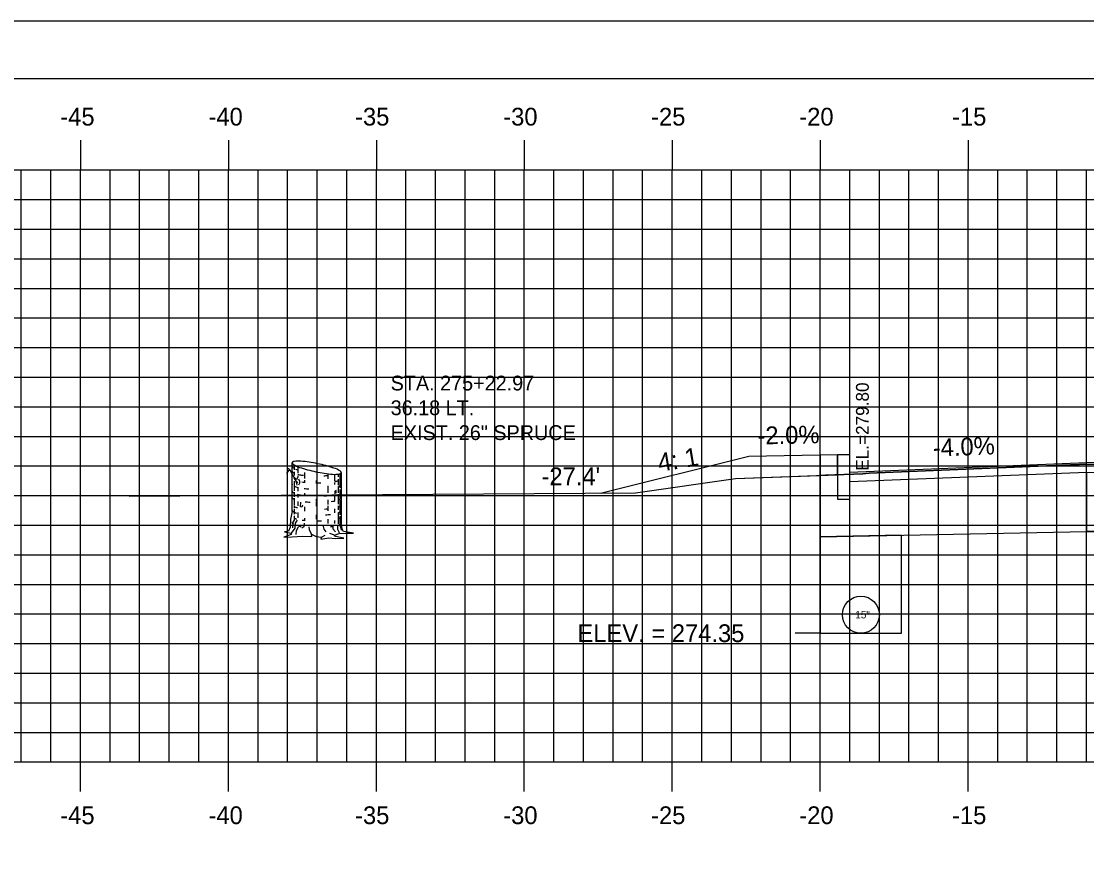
# Model space of a CAD drawing. Extents: x 853340 to 853510, y 366268 to 366378.
# Drawn here: x 853376.1 to 853412.11, y 366350.13 to 366378.18 of the extents above; entities that cross this region are included whole.
import ezdxf

# ---------------------------------------------------------------- set-up
doc = ezdxf.new("R2010")
doc.units = 0
for name, color, linetype in [('ANNOTATION', 7, 'Continuous'), ('BORDER', 7, 'Continuous'), ('D_Curb_Type_1_Lt', 7, 'Continuous'), ('D_Roadway_Edge_TW', 7, 'Continuous'), ('D_Roadway_FinishedGrade', 7, 'Continuous'), ('D_Roadway_SubGrade', 7, 'Continuous'), ('D_Text_Monospaced', 7, 'Continuous'), ('D_Text_Standard', 7, 'Continuous'), ('H_V ANNOTATION', 7, 'Continuous'), ('JUNK COM EXC', 7, 'Continuous'), ('JUNK FILL', 7, 'Continuous'), ('junk strct exc', 7, 'Continuous'), ('MAJOR', 7, 'Continuous'), ('MINOR', 7, 'Continuous'), ('PDRAIN', 7, 'Continuous'), ('PLOT BOUNDARY', 7, 'Continuous'), ('S_Roadway_Centerline', 7, 'Continuous'), ('S_Trees_Conifer_Pay', 7, 'Continuous')]:
    doc.layers.add(name, color=color, linetype=linetype)

msp = doc.modelspace()

# ---------------------------------------------------------------- linework, layer by layer
at = {"layer": 'BORDER'}
msp.add_line((853508.1, 366376.236), (853348.1, 366376.236), dxfattribs=at)
at = {"layer": 'D_Curb_Type_1_Lt'}
msp.add_lwpolyline([(853403.683, 366363.536), (853403.683, 366362.036), (853404.1, 366362.036), (853404.1, 366363.536)], close=True, dxfattribs=at)
at = {"layer": 'D_Roadway_Edge_TW'}
msp.add_lwpolyline([(853404.1, 366362.952), (853412.1, 366363.272), (853423.1, 366363.28), (853434.1, 366363.06), (853442.1, 366362.74)], dxfattribs=at)
at = {"layer": 'D_Roadway_FinishedGrade'}
msp.add_line((853400.683, 366363.476), (853395.722, 366362.235), dxfattribs=at)
msp.add_lwpolyline([(853403.683, 366363.536), (853400.683, 366363.476)], dxfattribs=at)
at = {"layer": 'D_Roadway_SubGrade'}
for points in [[(853403.1, 366363.524), (853403.1, 366360.759)], [(853403.1, 366360.759), (853412.107, 366360.939), (853412.107, 366362.939), (853404.1, 366362.619)]]:
    msp.add_lwpolyline(points, dxfattribs=at)
msp.add_lwpolyline([(853412.107, 366360.939), (853412.107, 366362.939), (853423.107, 366362.947), (853434.107, 366362.727), (853434.107, 366360.727), (853423.107, 366360.947)], close=True, dxfattribs=at)
at = {"layer": 'D_Text_Standard'}
msp.add_lwpolyline([(853403.1, 366357.506), (853402.939, 366357.506), (853402.259, 366357.506)], dxfattribs=at)
at = {"layer": 'JUNK COM EXC'}
msp.add_lwpolyline([(853403.1, 366362.838), (853403.1, 366360.759), (853412.107, 366360.939), (853423.107, 366360.947), (853443.101, 366360.548), (853443.1, 366362.612), (853435.895, 366362.863), (853428.824, 366363.051), (853423.1, 366363.253), (853411.854, 366363.201), (853411.562, 366363.195), (853404.759, 366362.908), (853404.544, 366362.894), (853403.28, 366362.845), (853403.1, 366362.838)], dxfattribs=at)
at = {"layer": 'JUNK FILL'}
msp.add_lwpolyline([(853403.683, 366362.861), (853403.683, 366363.536), (853400.683, 366363.476), (853395.722, 366362.235), (853396.858, 366362.243), (853400.236, 366362.728)], close=True, dxfattribs=at)
at = {"layer": 'junk strct exc'}
msp.add_lwpolyline([(853403.1, 366360.759), (853403.1, 366357.506), (853405.85, 366357.506), (853405.85, 366360.814)], close=True, dxfattribs=at)
at = {"layer": 'MAJOR'}
for p, q in [((853378.1, 366374.158), (853378.1, 366373.156)), ((853383.1, 366374.158), (853383.1, 366373.156)), ((853388.1, 366374.158), (853388.1, 366373.156)), ((853393.1, 366374.158), (853393.1, 366373.156)), ((853398.1, 366374.158), (853398.1, 366373.156)), ((853403.1, 366374.158), (853403.1, 366373.156)), ((853408.1, 366374.158), (853408.1, 366373.156)), ((853353.1, 366373.156), (853493.1, 366373.156)), ((853353.1, 366373.156), (853493.1, 366373.156)), ((853378.1, 366353.156), (853378.1, 366373.156)), ((853383.1, 366353.156), (853383.1, 366373.156)), ((853388.1, 366353.156), (853388.1, 366373.156)), ((853393.1, 366353.156), (853393.1, 366373.156)), ((853398.1, 366353.156), (853398.1, 366373.156)), ((853403.1, 366353.156), (853403.1, 366373.156)), ((853408.1, 366353.156), (853408.1, 366373.156)), ((853353.1, 366368.156), (853493.1, 366368.156)), ((853353.1, 366363.156), (853493.1, 366363.156)), ((853353.1, 366358.156), (853493.1, 366358.156)), ((853353.1, 366353.156), (853493.1, 366353.156)), ((853353.1, 366353.156), (853493.1, 366353.156)), ((853378.1, 366352.154), (853378.1, 366353.156)), ((853383.1, 366352.154), (853383.1, 366353.156)), ((853388.1, 366352.154), (853388.1, 366353.156)), ((853393.1, 366352.154), (853393.1, 366353.156)), ((853398.1, 366352.154), (853398.1, 366353.156)), ((853403.1, 366352.154), (853403.1, 366353.156)), ((853408.1, 366352.154), (853408.1, 366353.156))]:
    msp.add_line(p, q, dxfattribs=at)
at = {"layer": 'MINOR'}
for p, q in [((853376.1, 366353.156), (853376.1, 366373.156)), ((853377.1, 366353.156), (853377.1, 366373.156)), ((853379.1, 366353.156), (853379.1, 366373.156)), ((853380.1, 366353.156), (853380.1, 366373.156)), ((853381.1, 366353.156), (853381.1, 366373.156)), ((853382.1, 366353.156), (853382.1, 366373.156)), ((853384.1, 366353.156), (853384.1, 366373.156)), ((853385.1, 366353.156), (853385.1, 366373.156)), ((853386.1, 366353.156), (853386.1, 366373.156)), ((853387.1, 366353.156), (853387.1, 366373.156)), ((853389.1, 366353.156), (853389.1, 366373.156)), ((853390.1, 366353.156), (853390.1, 366373.156)), ((853391.1, 366353.156), (853391.1, 366373.156)), ((853392.1, 366353.156), (853392.1, 366373.156)), ((853394.1, 366353.156), (853394.1, 366373.156)), ((853395.1, 366353.156), (853395.1, 366373.156)), ((853396.1, 366353.156), (853396.1, 366373.156)), ((853397.1, 366353.156), (853397.1, 366373.156)), ((853399.1, 366353.156), (853399.1, 366373.156)), ((853400.1, 366353.156), (853400.1, 366373.156)), ((853401.1, 366353.156), (853401.1, 366373.156)), ((853402.1, 366353.156), (853402.1, 366373.156)), ((853404.1, 366353.156), (853404.1, 366373.156)), ((853405.1, 366353.156), (853405.1, 366373.156)), ((853406.1, 366353.156), (853406.1, 366373.156)), ((853407.1, 366353.156), (853407.1, 366373.156)), ((853409.1, 366353.156), (853409.1, 366373.156)), ((853410.1, 366353.156), (853410.1, 366373.156)), ((853411.1, 366353.156), (853411.1, 366373.156)), ((853412.1, 366353.156), (853412.1, 366373.156)), ((853353.1, 366372.156), (853493.1, 366372.156)), ((853353.1, 366371.156), (853493.1, 366371.156)), ((853353.1, 366370.156), (853493.1, 366370.156)), ((853353.1, 366369.156), (853493.1, 366369.156)), ((853353.1, 366367.156), (853493.1, 366367.156)), ((853353.1, 366366.156), (853493.1, 366366.156)), ((853353.1, 366365.156), (853493.1, 366365.156)), ((853353.1, 366364.156), (853493.1, 366364.156)), ((853353.1, 366362.156), (853493.1, 366362.156)), ((853353.1, 366361.156), (853493.1, 366361.156)), ((853353.1, 366360.156), (853493.1, 366360.156)), ((853353.1, 366359.156), (853493.1, 366359.156)), ((853353.1, 366357.156), (853493.1, 366357.156)), ((853353.1, 366356.156), (853493.1, 366356.156)), ((853353.1, 366355.156), (853493.1, 366355.156)), ((853353.1, 366354.156), (853493.1, 366354.156))]:
    msp.add_line(p, q, dxfattribs=at)
at = {"layer": 'PDRAIN'}
msp.add_lwpolyline([(853403.1, 366360.759), (853403.1, 366357.506), (853405.85, 366357.506), (853405.85, 366360.814)], dxfattribs=at)
msp.add_circle((853404.475, 366358.131), 0.625, dxfattribs=at)
at = {"layer": 'PLOT BOUNDARY'}
msp.add_lwpolyline([(853340.007, 366268.177), (853510.007, 366268.177), (853510.007, 366378.177), (853340.007, 366378.177)], close=True, dxfattribs=at)
at = {"layer": 'S_Roadway_Centerline'}
msp.add_lwpolyline([(853379.745, 366362.132), (853396.858, 366362.243), (853400.236, 366362.728), (853403.28, 366362.845), (853404.544, 366362.894), (853404.759, 366362.908), (853411.562, 366363.195), (853411.854, 366363.201), (853423.1, 366363.253), (853428.824, 366363.051), (853435.895, 366362.863), (853448.102, 366362.438), (853448.825, 366362.419), (853451.873, 366362.862), (853452.264, 366362.884), (853453.558, 366362.897), (853453.702, 366362.932), (853455.448, 366363.065), (853466.573, 366363.351)], dxfattribs=at)
at = {"layer": 'S_Trees_Conifer_Pay'}
for p, q in [((853385.252, 366361.618), (853385.252, 366363.265)), ((853385.323, 366363.193), (853385.323, 366363.03)), ((853385.441, 366363.132), (853385.441, 366362.909)), ((853385.323, 366362.963), (853385.323, 366362.835)), ((853385.441, 366362.82), (853385.441, 366362.773)), ((853385.669, 366362.936), (853385.669, 366362.736)), ((853386.465, 366362.894), (853386.465, 366362.726)), ((853386.685, 366362.873), (853386.685, 366362.641)), ((853386.81, 366362.881), (853386.81, 366362.784)), ((853386.869, 366362.892), (853386.869, 366362.421)), ((853386.916, 366361.208), (853386.916, 366362.93)), ((853385.323, 366362.648), (853385.323, 366362.312)), ((853385.384, 366362.637), (853385.435, 366362.577)), ((853385.441, 366362.438), (853385.441, 366362.306)), ((853385.669, 366362.679), (853385.669, 366362.59)), ((853386.06, 366362.662), (853386.06, 366362.567)), ((853386.465, 366362.489), (853386.465, 366362.252)), ((853386.685, 366362.6), (853386.685, 366362.526)), ((853386.81, 366362.709), (853386.81, 366362.505)), ((853386.81, 366362.448), (853386.81, 366362.248)), ((853385.323, 366362.275), (853385.323, 366362.112)), ((853385.323, 366362.065), (853385.323, 366361.848)), ((853385.441, 366362.195), (853385.441, 366362.085)), ((853385.669, 366362.242), (853385.669, 366362.137)), ((853386.06, 366362.049), (853386.06, 366361.974)), ((853386.685, 366362.123), (853386.685, 366361.984)), ((853386.81, 366362.201), (853386.81, 366361.865)), ((853386.869, 366362.357), (853386.869, 366362.049)), ((853385.323, 366361.818), (853385.323, 366361.744)), ((853385.323, 366361.703), (853385.323, 366361.53)), ((853385.441, 366361.95), (853385.441, 366361.808)), ((853385.669, 366361.77), (853385.669, 366361.624)), ((853386.06, 366361.95), (853386.06, 366361.801)), ((853386.465, 366362.007), (853386.465, 366361.855)), ((853386.465, 366361.812), (853386.465, 366361.639)), ((853386.685, 366361.713), (853386.685, 366361.571)), ((853386.81, 366361.812), (853386.81, 366361.676)), ((853386.869, 366362.001), (853386.869, 366361.509)), ((853385.441, 366361.581), (853385.441, 366361.408)), ((853385.669, 366361.392), (853385.669, 366361.303)), ((853386.06, 366361.509), (853386.06, 366361.356)), ((853386.465, 366361.361), (853386.465, 366361.208)), ((853386.81, 366361.577), (853386.81, 366361.198)), ((853386.869, 366361.455), (853386.869, 366361.208)), ((853386.685, 366361.309), (853386.685, 366361.215)), ((853386.248, 366360.751), (853386.374, 366360.815)), ((853386.685, 366360.815), (853386.522, 366360.879))]:
    msp.add_line(p, q, dxfattribs=at)
for points in [[(853385.206, 366362.996), (853385.131, 366363.004), (853385.058, 366362.905)], [(853385.435, 366362.763), (853385.398, 366362.689), (853385.351, 366362.746), (853385.293, 366362.814), (853385.201, 366363.008), (853385.136, 366363.055), (853385.106, 366363.062)], [(853385.421, 366362.51), (853385.384, 366362.637), (853385.32, 366362.753), (853385.289, 366362.82), (853385.22, 366362.967)], [(853385.468, 366362.726), (853385.499, 366362.641), (853385.503, 366362.574), (853385.472, 366362.51)], [(853386.737, 366362.236), (853386.743, 366362.331), (853386.699, 366362.308), (853386.699, 366362.213)], [(853385.598, 366361.837), (853385.585, 366361.76), (853385.538, 366361.77), (853385.551, 366361.937)], [(853385.252, 366361.618), (853385.201, 366361.356), (853385.184, 366361.083), (853385.127, 366360.957), (853384.991, 366360.927), (853385.221, 366360.889), (853385.221, 366360.889), (853385.215, 366360.842), (853384.968, 366360.747), (853385.242, 366360.764), (853385.598, 366360.784), (853385.919, 366360.774), (853385.913, 366360.856), (853386.061, 366360.774), (853386.248, 366360.751), (853386.224, 366360.683), (853386.491, 366360.726), (853386.712, 366360.7), (853387.005, 366360.717), (853386.716, 366360.774), (853386.685, 366360.815), (853386.848, 366360.873), (853387.085, 366360.883), (853387.325, 366360.883), (853386.984, 366360.941), (853386.942, 366361.021), (853386.916, 366361.208)], [(853385.425, 366361.33), (853385.351, 366361.225), (853385.346, 366361.052), (853385.221, 366360.889)], [(853385.326, 366361.476), (853385.32, 366361.33), (853385.273, 366361.262), (853385.262, 366361.062)], [(853385.384, 366360.836), (853385.398, 366360.974), (853385.472, 366361.103)], [(853385.662, 366361.225), (853385.652, 366361.099), (853385.577, 366361.056)], [(853385.913, 366360.856), (853385.839, 366360.998), (853385.829, 366361.099)], [(853386.401, 366360.927), (853386.333, 366361.021), (853386.306, 366361.161)], [(853386.627, 366361.167), (853386.627, 366361.035), (853386.716, 366360.936)], [(853386.79, 366361.14), (853386.784, 366361.025), (853386.837, 366360.936), (853386.848, 366360.873)], [(853386.868, 366361.161), (853386.889, 366361.083), (853386.909, 366360.988)]]:
    msp.add_lwpolyline(points, dxfattribs=at)
for centre, radius, start, end in [((853385.275, 366363.265), 0.0226, 156.5926, 168.2806), ((853385.275, 366363.265), 0.0226, 168.2806, 179.9685), ((853385.278, 366363.265), 0.0264, 179.9685, 190.7806), ((853385.283, 366363.266), 0.0314, 190.7806, 203.4842), ((853385.285, 366363.139), 0.0334, 185.7849, 196.0515), ((853385.295, 366363.142), 0.0441, 196.0515, 210), ((853385.278, 366363.264), 0.0264, 145.7806, 156.5926), ((853385.303, 366363.275), 0.0527, 203.4842, 213.2806), ((853385.282, 366363.261), 0.0314, 133.077, 145.7806), ((853385.311, 366363.151), 0.0624, 210, 228.7494), ((853385.327, 366363.291), 0.0817, 213.2806, 227.6113), ((853385.297, 366363.245), 0.0527, 123.2806, 133.077), ((853385.313, 366363.221), 0.0817, 108.9499, 123.2806), ((853385.441, 366363.415), 0.251, 227.6113, 235.7806), ((853385.367, 366363.062), 0.251, 100.7806, 108.9499), ((853385.751, 366363.871), 0.802, 235.7806, 251.9406), ((853385.47, 366362.52), 0.802, 84.6206, 100.7806), ((853385.06, 366358.162), 5.179, 78.2806, 84.6206), ((853385.06, 366358.162), 5.179, 71.9406, 78.2806), ((853385.285, 366362.984), 0.0334, 185.7849, 196.0515), ((853385.295, 366362.987), 0.0441, 196.0515, 210), ((853385.311, 366362.997), 0.0624, 210, 228.7494), ((853385.384, 366363.234), 0.172, 228.7494, 240), ((853385.384, 366363.079), 0.172, 228.7494, 240), ((853385.583, 366363.424), 0.571, 240, 242.9763), ((853385.583, 366363.579), 0.571, 247.5868, 255.5683), ((853385.583, 366363.424), 0.571, 255.6333, 261.8968), ((853387.108, 366368.033), 5.179, 251.9406, 258.2806), ((853386.084, 366366.942), 4.124, 261.8968, 263.762), ((853387.108, 366368.033), 5.179, 258.2806, 264.6206), ((853386.084, 366366.942), 4.124, 273.2669, 275.3045), ((853386.697, 366363.675), 0.802, 264.6206, 280.7806), ((853386.417, 366362.324), 0.802, 55.7806, 71.9406), ((853386.8, 366363.133), 0.251, 280.7806, 288.9499), ((853386.727, 366362.78), 0.251, 47.6113, 55.7806), ((853386.855, 366362.974), 0.0817, 288.9499, 303.2806), ((853386.841, 366362.904), 0.0817, 33.2806, 47.6113), ((853386.871, 366362.949), 0.0527, 303.2806, 313.077), ((853386.886, 366362.934), 0.0314, 313.077, 325.7806), ((853386.865, 366362.92), 0.0527, 23.4842, 33.2806), ((853386.89, 366362.931), 0.0264, 325.7806, 336.5926), ((853386.885, 366362.929), 0.0314, 10.7806, 23.4842), ((853386.893, 366362.93), 0.0226, 336.5926, 348.2806), ((853386.889, 366362.93), 0.0264, 359.9685, 10.7806), ((853386.893, 366362.93), 0.0226, 348.2806, 359.9685), ((853386.884, 366362.752), 0.0334, 0, 16.0515), ((853385.285, 366362.541), 0.0334, 185.7849, 196.0515), ((853385.583, 366362.98), 0.571, 242.9571, 255.5507), ((853386.085, 366366.709), 4.124, 262.9442, 264.2151), ((853386.084, 366366.498), 4.124, 264.0496, 266.2948), ((853386.085, 366366.709), 4.124, 269.6419, 270), ((853386.085, 366366.709), 4.124, 270, 271.9249), ((853386.586, 366363.191), 0.571, 282.0154, 293.1403), ((853386.585, 366362.98), 0.571, 292.9413, 300), ((853386.586, 366363.191), 0.571, 299.6633, 300), ((853386.785, 366362.846), 0.172, 300, 311.2506), ((853386.858, 366362.764), 0.0624, 311.2506, 330), ((853386.873, 366362.755), 0.0441, 330, 343.9485), ((853386.884, 366362.752), 0.0334, 343.9485, 360), ((853385.287, 366362.305), 0.0334, 185.7849, 196.0515), ((853385.287, 366362.095), 0.0334, 185.7849, 196.0515), ((853385.297, 366362.308), 0.0441, 196.0515, 210), ((853385.297, 366362.098), 0.0441, 196.0515, 210), ((853385.313, 366362.317), 0.0624, 210, 228.7494), ((853385.313, 366362.107), 0.0624, 210, 228.7494), ((853385.385, 366362.4), 0.172, 228.7494, 240), ((853385.385, 366362.189), 0.172, 228.7494, 240), ((853385.584, 366362.745), 0.571, 240, 242.8104), ((853385.584, 366362.535), 0.571, 240, 242.8104), ((853385.584, 366362.745), 0.571, 253.0704, 261.8968), ((853386.085, 366366.262), 4.124, 261.8968, 262.3875), ((853386.085, 366366.262), 4.124, 273.3324, 275.919), ((853386.586, 366362.535), 0.571, 293.1403, 300), ((853386.586, 366362.745), 0.571, 299.6633, 300), ((853386.785, 366362.4), 0.172, 300, 311.2506), ((853386.785, 366362.189), 0.172, 300, 311.2506), ((853386.858, 366362.317), 0.0624, 311.2506, 330), ((853386.858, 366362.107), 0.0624, 311.2506, 330), ((853386.873, 366362.308), 0.0441, 330, 343.9485), ((853386.873, 366362.098), 0.0441, 330, 343.9485), ((853386.884, 366362.305), 0.0334, 0, 16.0515), ((853386.884, 366362.305), 0.0334, 343.9485, 360), ((853386.884, 366362.095), 0.0334, 0, 16.0515), ((853386.884, 366362.095), 0.0334, 343.9485, 360), ((853385.584, 366362.298), 0.571, 242.8104, 254.6017), ((853386.085, 366366.052), 4.124, 264.5431, 266.8507), ((853386.085, 366366.052), 4.124, 269.6419, 270), ((853386.085, 366365.815), 4.124, 273.6807, 275.284), ((853386.085, 366366.052), 4.124, 276.8526, 278.1032), ((853386.586, 366362.535), 0.571, 278.1032, 280.7293), ((853386.586, 366362.298), 0.571, 293.1403, 300), ((853386.785, 366361.953), 0.172, 300, 311.2506), ((853386.858, 366361.87), 0.0624, 311.2506, 330), ((853386.873, 366361.861), 0.0441, 330, 343.9485), ((853386.884, 366361.858), 0.0334, 0, 16.0515), ((853386.884, 366361.858), 0.0334, 343.9485, 360), ((853385.287, 366361.66), 0.0334, 185.7849, 196.0515), ((853385.297, 366361.663), 0.0441, 196.0515, 210), ((853385.313, 366361.672), 0.0624, 210, 228.7494), ((853385.385, 366361.755), 0.172, 228.7494, 240), ((853385.584, 366362.1), 0.571, 240, 250.7093), ((853385.584, 366361.905), 0.571, 242.7279, 251.4933), ((853386.085, 366365.422), 4.124, 263.2104, 264.2151), ((853386.085, 366365.618), 4.124, 274.1603, 276.5009), ((853386.597, 366362.106), 0.571, 291.9732, 298.7631), ((853386.586, 366361.905), 0.571, 293.1403, 300), ((853386.785, 366361.559), 0.172, 300, 311.2506), ((853386.858, 366361.477), 0.0624, 311.2506, 330), ((853386.873, 366361.468), 0.0441, 330, 343.9485), ((853386.884, 366361.66), 0.0334, 0, 16.0515), ((853386.884, 366361.465), 0.0334, 0, 16.0515), ((853386.884, 366361.465), 0.0334, 343.9485, 360), ((853385.287, 366361.244), 0.0334, 185.7849, 196.0515), ((853385.297, 366361.247), 0.0441, 196.0515, 210), ((853385.313, 366361.257), 0.0624, 210, 228.7494), ((853385.385, 366361.339), 0.172, 228.7494, 240), ((853385.584, 366361.684), 0.571, 258.363, 261.8968), ((853386.085, 366365.202), 4.124, 261.8968, 262.6316), ((853386.085, 366365.422), 4.124, 269.8672, 270), ((853386.085, 366365.422), 4.124, 270, 272.1883), ((853386.085, 366365.202), 4.124, 276.488, 277.5562), ((853386.586, 366361.684), 0.571, 295.4686, 300), ((853386.785, 366361.339), 0.172, 300, 311.2506), ((853386.858, 366361.257), 0.0624, 311.2506, 330), ((853386.873, 366361.247), 0.0441, 330, 343.9485), ((853386.884, 366361.244), 0.0334, 0, 16.0515), ((853386.884, 366361.244), 0.0334, 343.9485, 360)]:
    msp.add_arc(centre, radius, start, end, dxfattribs=at)

# ---------------------------------------------------------------- texts
at = {"layer": 'ANNOTATION'}
for s, height, rotation, p in [('-2.0%', 0.6, 1.1458, (853400.986, 366363.882)), ('-4.0%', 0.6, 2.2906, (853406.916, 366363.466)), ('4: 1', 0.6188, 9.4623, (853397.665, 366362.954))]:
    msp.add_text(s, height=height, rotation=rotation, dxfattribs=at).set_placement(p)
at = {"layer": 'D_Text_Monospaced'}
for s, height, p in [('STA. 275+22.97', 0.49998, (853388.583, 366365.706)), ('36.18 LT.', 0.5, (853388.583, 366364.872)), ('EXIST. 26" SPRUCE', 0.49998, (853388.583, 366364.032))]:
    msp.add_text(s, height=height, dxfattribs=at).set_placement(p)
at = {"layer": 'D_Text_Standard'}
msp.add_text(' EL.=279.80', height=0.4335, rotation=90, dxfattribs=at).set_placement((853404.743, 366362.834))
for s, p in [("-27.4'", (853393.68, 366362.505)), ('ELEV. = 274.35', (853394.896, 366357.206))]:
    msp.add_text(s, height=0.6, dxfattribs=at).set_placement(p)
at = {"layer": 'H_V ANNOTATION'}
for s, p in [('-45', (853377.417, 366374.656)), ('-40', (853382.425, 366374.656)), ('-35', (853387.38, 366374.656)), ('-30', (853392.388, 366374.656)), ('-25', (853397.385, 366374.656)), ('-20', (853402.393, 366374.656)), ('-15', (853407.557, 366374.656)), ('-45', (853377.417, 366351.056)), ('-40', (853382.425, 366351.056)), ('-35', (853387.38, 366351.056)), ('-30', (853392.388, 366351.056)), ('-25', (853397.385, 366351.056)), ('-20', (853402.393, 366351.056)), ('-15', (853407.557, 366351.056))]:
    msp.add_text(s, height=0.6, dxfattribs=at).set_placement(p)
at = {"layer": 'PDRAIN'}
msp.add_text('15"', height=0.25, dxfattribs=at).set_placement((853404.288, 366358.006))

doc.saveas('drawing.dxf')
